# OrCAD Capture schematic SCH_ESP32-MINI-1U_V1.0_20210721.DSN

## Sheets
1 01_DesignBlock: title: <ESP32-MINI-1U>; rev: V1.0; note: <01_DesignBlock>
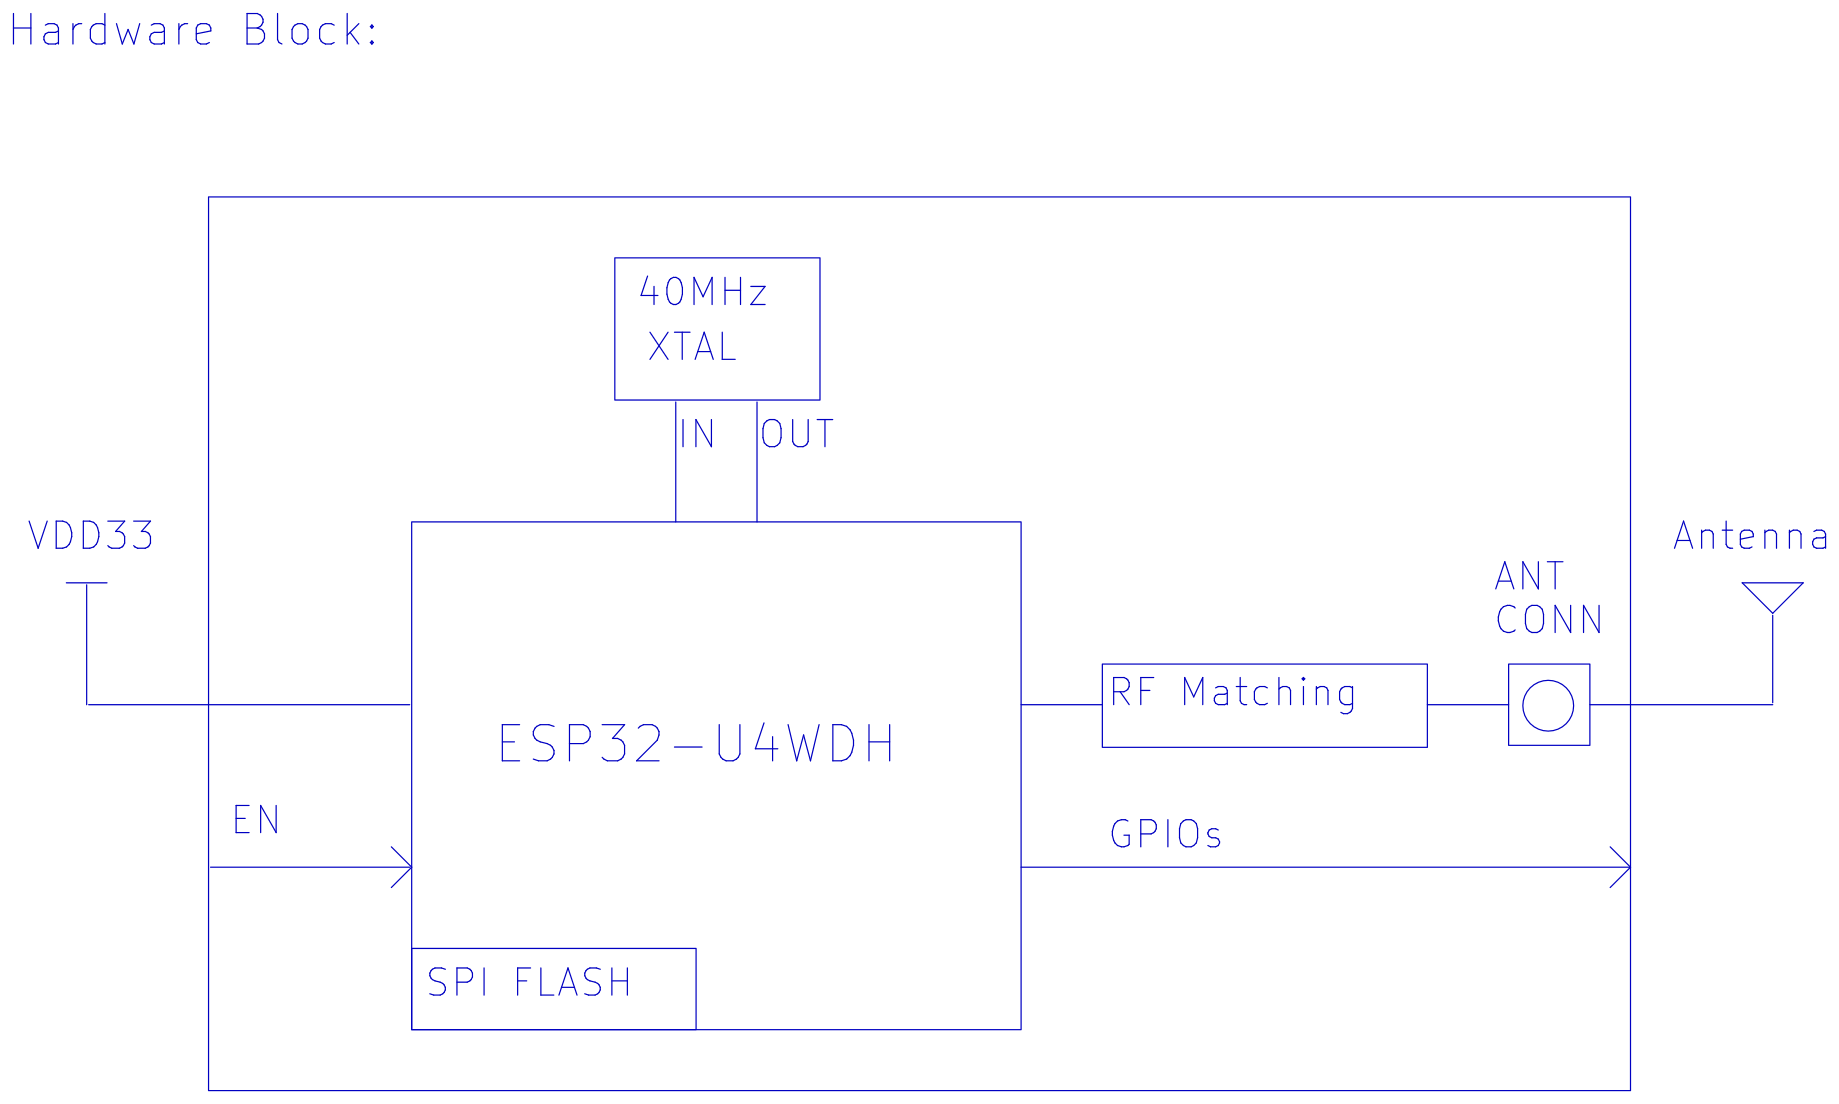
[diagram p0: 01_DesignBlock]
2 02_ESP32-MINI-1U: size A4; note: <02_ESP32-MINI-1U>
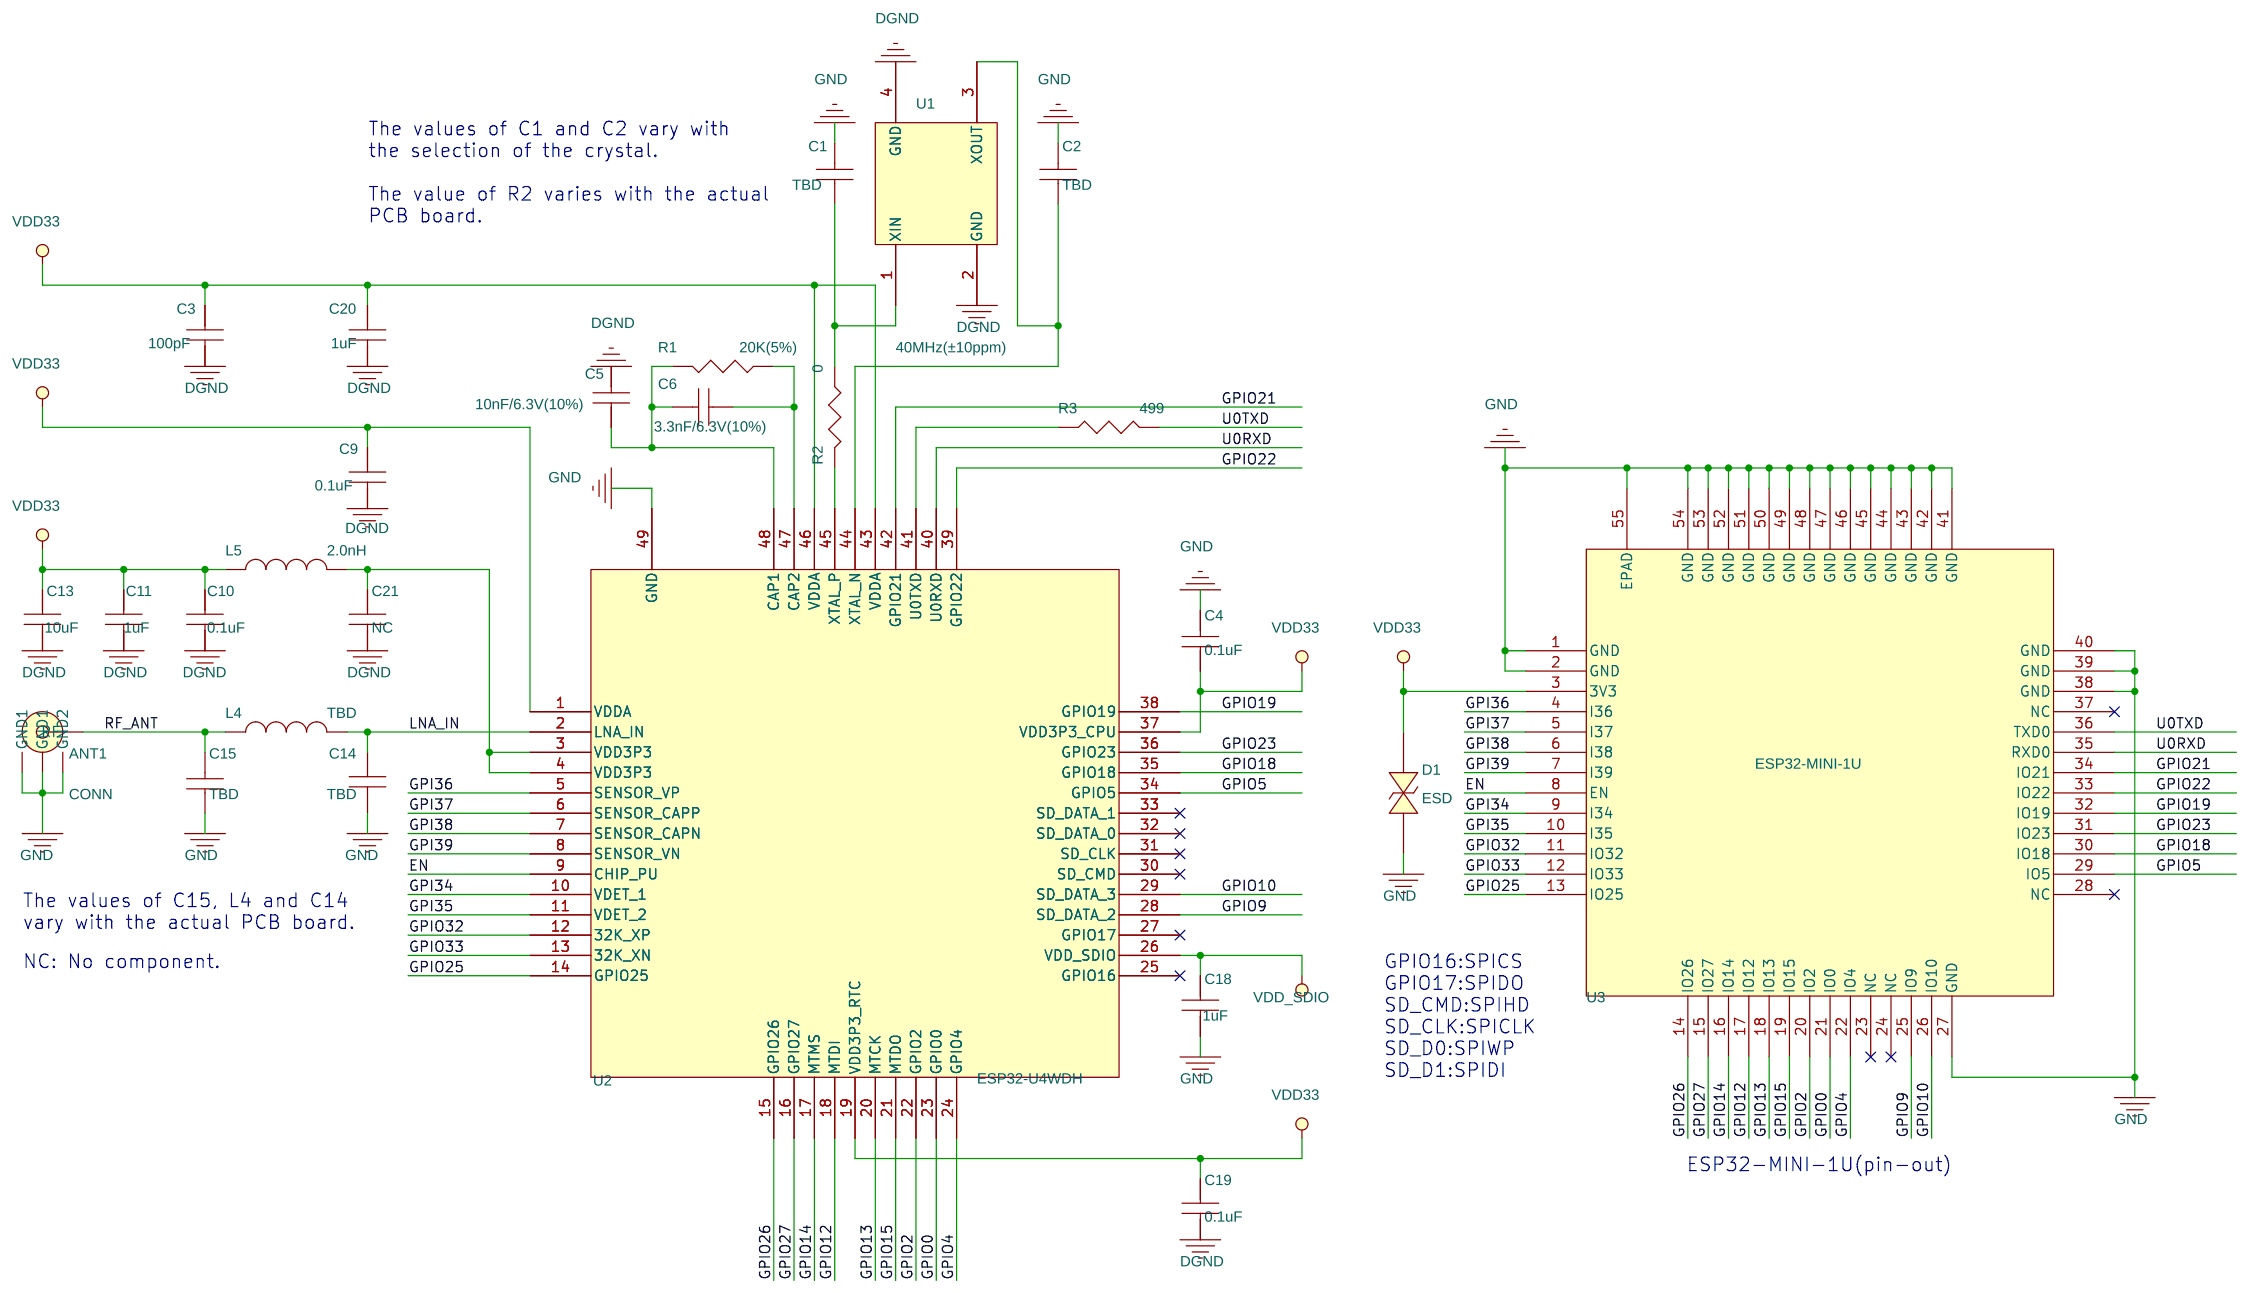
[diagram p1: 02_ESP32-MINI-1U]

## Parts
ANT1  CONN  [MINI-ANT-TYPED]
C1  TBD  [C0201]
C2  TBD  [C0201]
C3  100pF  [C0201]
C4  0.1uF  [C0201]
C5  10nF/6.3V(10%)  [C0201]
C6  3.3nF/6.3V(10%)  [C0201]
C9  0.1uF  [C0201]
C10  0.1uF  [C0201]
C11  1uF  [C0201]
C13  10uF  [c0402]
C14  TBD  [C0201]
C15  TBD  [C0201]
C18  1uF  [C0201]
C19  0.1uF  [C0201]
C20  1uF  [C0201]
C21  NC  [C0201]
D1  ESD  [SOD882]
L4  TBD  [L0201]
L5  2.0nH  [L0201]
R1  20K(5%)  [R0201]
R2  0  [R0201]
R3  499  [R0201]
U1  40MHz(±10ppm)  [XTAL3225]
U2  ESP32-U4WDH  [QFN48EB_0P35_5]
U3  ESP32-MINI-1U  [QFN54_0P8_11P8X12P1]

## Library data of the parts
ANT1 = IPEX_4P
C1-C6 C9-C11 C13-C15 C18-C21 = CAP
D1 = DIODE_BI-DIR_TRIG
L4 L5 = Inductor
R1-R3 = RESISTOR_0
U1 = X1_1
U2 = ESP32
U3 = ESP32-MINI-1

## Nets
GND: ANT1.2(GND2) ANT1.3(GND1) ANT1.4(GND1) C1.2 C2.2 C3.2 C4.2 C5.2 C9.2 C10.2 C11.2 C13.2 C14.2 C15.1 C18.2 C19.2 C20.2 C21.2 D1.2 U1.2(GND) U1.4(GND) U2.49(GND) U3.1(GND) U3.2(GND) U3.27(GND) U3.38(GND) U3.39(GND) U3.40(GND) U3.41(GND) U3.42(GND) U3.43(GND) U3.44(GND) U3.45(GND) U3.46(GND) U3.47(GND) U3.48(GND) U3.49(GND) U3.50(GND) U3.51(GND) U3.52(GND) U3.53(GND) U3.54(GND) U3.55(EPAD)
VDD33: C3.1 C4.1 C9.1 C10.1 C11.1 C13.1 C19.1 C20.1 D1.1 L5.2 U2.1(VDDA) U2.19(VDD3P3_RTC) U2.37(VDD3P3_CPU) U2.43(VDDA) U2.46(VDDA) U3.3(3V3)
VDD_SDIO: C18.1 U2.26(VDD_SDIO)
EN: U2.9(CHIP_PU) U3.8(EN)
GPI34: U2.10(VDET_1) U3.9(I34)
GPI35: U2.11(VDET_2) U3.10(I35)
GPI36: U2.5(SENSOR_VP) U3.4(I36)
GPI37: U2.6(SENSOR_CAPP) U3.5(I37)
GPI38: U2.7(SENSOR_CAPN) U3.6(I38)
GPI39: U2.8(SENSOR_VN) U3.7(I39)
GPIO0: U2.23(GPIO0) U3.21(IO0)
GPIO2: U2.22(GPIO2) U3.20(IO2)
GPIO4: U2.24(GPIO4) U3.22(IO4)
GPIO5: U2.34(GPIO5) U3.29(IO5)
GPIO9: U2.28(SD_DATA_2) U3.25(IO9)
GPIO10: U2.29(SD_DATA_3) U3.26(IO10)
GPIO12: U2.18(MTDI) U3.17(IO12)
GPIO13: U2.20(MTCK) U3.18(IO13)
GPIO14: U2.17(MTMS) U3.16(IO14)
GPIO15: U2.21(MTDO) U3.19(IO15)
GPIO18: U2.35(GPIO18) U3.30(IO18)
GPIO19: U2.38(GPIO19) U3.32(IO19)
GPIO21: U2.42(GPIO21) U3.34(IO21)
GPIO22: U2.39(GPIO22) U3.33(IO22)
GPIO23: U2.36(GPIO23) U3.31(IO23)
GPIO25: U2.14(GPIO25) U3.13(IO25)
GPIO26: U2.15(GPIO26) U3.14(IO26)
GPIO27: U2.16(GPIO27) U3.15(IO27)
GPIO32: U2.12(32K_XP) U3.11(IO32)
GPIO33: U2.13(32K_XN) U3.12(IO33)
LNA_IN: C14.1 L4.1 U2.2(LNA_IN)
RF_ANT: ANT1.1(RF) C15.2 L4.2
U0RXD: U2.40(U0RXD) U3.35(RXD0)
U0TXD: R3.2 U3.36(TXD0)
N16455819: C21.1 L5.1 U2.3(VDD3P3) U2.4(VDD3P3)
N16693960: R3.1 U2.41(U0TXD)
N16694273: C2.1 U1.3(XOUT) U2.44(XTAL_N)
N16694289: C1.1 R2.1 U1.1(XIN)
N16694645: C6.1 R1.1 U2.47(CAP2)
N16694653: C5.1 C6.2 R1.2 U2.48(CAP1)
N16823909: R2.2 U2.45(XTAL_P)

Not connected (* = marked no-connect by the designer): U2 25(GPIO16)* 27(GPIO17)* 30(SD_CMD)* 31(SD_CLK)* 32(SD_DATA_0)* 33(SD_DATA_1)*; U3 23(NC)* 24(NC)* 28(NC)* 37(NC)*

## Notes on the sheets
sheet 1
- Hardware Block:
- 40MHz
- XTAL
- IN
- OUT
- VDD33
- Antenna
- ANT
  CONN
- RF Matching
- ESP32-U4WDH
- EN
- GPIOs
- SPI FLASH
sheet 2
- The values of C1 and C2 vary with
  the selection of the crystal.
  The value of R2 varies with the actual
  PCB board.
- The values of C15, L4 and C14
  vary with the actual PCB board.
- NC: No component.
- GPIO16:SPICS
  GPIO17:SPIDO
  SD_CMD:SPIHD
  SD_CLK:SPICLK
  SD_D0:SPIWP
  SD_D1:SPIDI
- ESP32-MINI-1U(pin-out)
